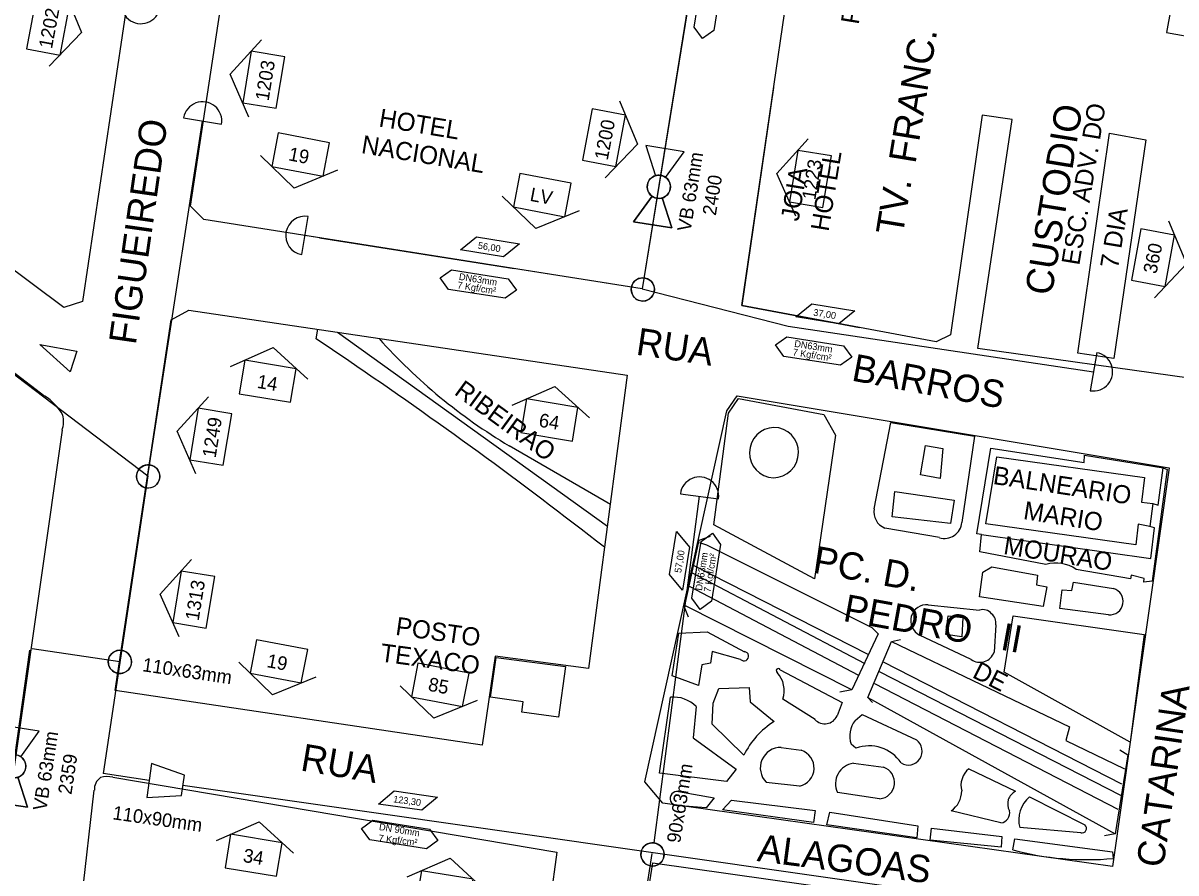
# Model space of a CAD drawing. Extents: x 325709 to 364434, y 7573432 to 7597073.
# Drawn here: x 338158.4 to 338412.3, y 7589570 to 7589757.3 of the extents above; entities that cross this region are included whole.
import ezdxf

# ---------------------------------------------------------------- set-up
doc = ezdxf.new("R2010")
doc.units = 0
for name, color, linetype in [('EDIFEXISTENT', 7, 'Continuous'), ('EDIFIDENTIF', 7, 'Continuous'), ('EDIFOBRAEXIS', 7, 'Continuous'), ('FORMATO', 7, 'Continuous'), ('LOGRADOURO', 7, 'Continuous'), ('LOGRADOURO_TEXTO', 7, 'Continuous'), ('NUM_REF', 7, 'Continuous'), ('SIMBOLO', 7, 'Continuous'), ('TEXTO', 7, 'Continuous'), ('TUBO_PEAD_GN_110', 7, 'Continuous'), ('TUBO_PEAD_GN_63', 7, 'Continuous'), ('TUBO_PEAD_GN_90', 7, 'Continuous'), ('VALVULA_PEAD_63', 7, 'Continuous'), ('VES - BLOQUEIIO', 7, 'Continuous')]:
    doc.layers.add(name, color=color, linetype=linetype)

# ---------------------------------------------------------------- blocks, each defined once
blk = doc.blocks.new('VALVULA_PEAD_DN_63')
at = {"layer": 'VALVULA_PEAD_63'}
for points in [[(-1.14, 0.57), (-4.25, 2.13), (-4.25, -2.13), (-1.14, -0.57)], [(-1.14, -0.57), (-4.25, -2.13), (-4.25, 2.13), (-1.14, 0.57)], [(1.14, -0.57), (4.25, -2.13), (4.25, 2.13), (1.14, 0.57)], [(1.14, -0.57), (4.25, -2.13), (4.25, 2.13), (1.14, 0.57)]]:
    blk.add_lwpolyline(points, dxfattribs=at)
blk.add_circle((0, 0), 1.28, dxfattribs=at)
for start, end in [(90, 270), (270, 90), (153.4349, 206.5651), (0, 26.5651), (333.4349, 0)]:
    blk.add_arc((0, 0), 1.28, start, end, dxfattribs=at)
blk = doc.blocks.new('INTERLIGACAO')
at = {"layer": 'SIMBOLO'}
blk.add_circle((0, 0), 1.28, dxfattribs=at)
for start, end in [(0, 180), (180, 0)]:
    blk.add_arc((0, 0), 1.28, start, end, dxfattribs=at)
blk = doc.blocks.new('NUM_REF')
at = {"layer": 'NUM_REF'}
blk.add_lwpolyline([(-4.3125, 0.9375), (0, 3.75), (4.3125, 0.9375)], dxfattribs=at)
blk.add_lwpolyline([(2.875, -1.875), (2.875, 1.875), (-2.875, 1.875), (-2.875, -1.875)], close=True, dxfattribs=at)

msp = doc.modelspace()

# ---------------------------------------------------------------- linework, layer by layer
at = {"layer": 'EDIFEXISTENT'}
for p, q in [((338323.68, 7589743.11), (338316.65, 7589695.04)), ((338390.66, 7589684.56), (338397.65, 7589733.03)), ((338397.65, 7589733.03), (338405.67, 7589731.58)), ((338405.67, 7589731.58), (338398.62, 7589683.41)), ((338223.69, 7589709.95), (338266.52, 7589703.2)), ((338316.65, 7589695.04), (338342.59, 7589690.19)), ((338398.62, 7589683.41), (338390.66, 7589684.56)), ((338356.03, 7589657.76), (338357.15, 7589664.2)), ((338357.15, 7589664.2), (338360.99, 7589663.58)), ((338360.99, 7589663.58), (338360.38, 7589656.96)), ((338370.46, 7589646.93), (338372.87, 7589661.74)), ((338372.87, 7589661.74), (338405.38, 7589657.14)), ((338360.38, 7589656.96), (338356.03, 7589657.76)), ((338405.38, 7589657.14), (338404.74, 7589651.72)), ((338349.81, 7589648.51), (338350.4, 7589654.06)), ((338350.4, 7589654.06), (338363.45, 7589652.17)), ((338363.45, 7589652.17), (338362.68, 7589647.01)), ((338404.74, 7589651.72), (338407.21, 7589651.43)), ((338407.21, 7589651.43), (338406.56, 7589646.34)), ((338362.68, 7589647.01), (338349.81, 7589648.51)), ((338403.45, 7589642.34), (338370.46, 7589646.93)), ((338403.97, 7589646.87), (338403.45, 7589642.34)), ((338406.56, 7589646.34), (338403.97, 7589646.87)), ((338304.04, 7589628.56), (338307.31, 7589643.34)), ((338307.31, 7589643.34), (338309.77, 7589644.2)), ((338304.97, 7589626.39), (338304.04, 7589628.56)), ((338361.62, 7589622.59), (338362.14, 7589626.66)), ((338362.14, 7589626.66), (338365.37, 7589626.29)), ((338365.37, 7589626.29), (338365.15, 7589622.07)), ((338345.31, 7589624.14), (338346.72, 7589622.72)), ((338346.72, 7589622.72), (338340.94, 7589610.37)), ((338344.4, 7589608.71), (338349.62, 7589621)), ((338349.62, 7589621), (338351.63, 7589621.49)), ((338365.15, 7589622.07), (338361.62, 7589622.59)), ((338261.32, 7589608.77), (338262.58, 7589617.5)), ((338262.58, 7589617.5), (338277.81, 7589615.53)), ((338277.81, 7589615.53), (338276.29, 7589604.36)), ((338340.94, 7589610.37), (338338.29, 7589609.88)), ((338268.55, 7589607.71), (338261.32, 7589608.77)), ((338268.2, 7589605.42), (338268.55, 7589607.71)), ((338345.45, 7589607.62), (338344.4, 7589608.71)), ((338276.29, 7589604.36), (338268.2, 7589605.42)), ((338401.67, 7589596.03), (338398.88, 7589578.64)), ((338399.94, 7589597.15), (338401.67, 7589596.03)), ((338398.88, 7589578.64), (338396.55, 7589578.2))]:
    msp.add_line(p, q, dxfattribs=at)
at = {"layer": 'EDIFOBRAEXIS'}
for p, q in [((338287.12, 7589646.39), (338227.63, 7589689.08)), ((338168.77, 7589680.42), (338162.09, 7589686.45)), ((338345.81, 7589650.28), (338349.48, 7589669.28)), ((338349.48, 7589669.28), (338367.93, 7589666.27)), ((338367.93, 7589666.27), (338365.14, 7589647.24)), ((338287.74, 7589651.18), (338265.42, 7589664.14)), ((338392.14, 7589662.08), (338409.52, 7589659.29)), ((338360.2, 7589643.9), (338348.16, 7589646.02)), ((338305.77, 7589636.16), (338343.74, 7589616.2)), ((338306.13, 7589637.78), (338344.44, 7589618.24)), ((338305.09, 7589633.22), (338342.38, 7589613.61)), ((338340.94, 7589610.37), (338304.16, 7589628.98)), ((338357.73, 7589629.12), (338369.05, 7589627.91)), ((338397.48, 7589626.91), (338386.69, 7589628.27)), ((338372.62, 7589624.72), (338372.26, 7589618.69)), ((338367.2, 7589617.07), (338355.82, 7589622.45)), ((338405.32, 7589622.54), (338402.25, 7589598.81)), ((338347.78, 7589616.52), (338400.32, 7589589.65)), ((338325.16, 7589614.79), (338338.79, 7589607.57)), ((338346.92, 7589614.41), (338400.08, 7589587.16)), ((338345.94, 7589611.76), (338399.53, 7589584.05)), ((338298.57, 7589592.02), (338300.98, 7589608.74)), ((338332.8, 7589603.84), (338325.74, 7589608.34)), ((338344.4, 7589608.71), (338398.88, 7589578.64)), ((338338.79, 7589607.57), (338337.65, 7589604.64)), ((338341.65, 7589603.59), (338343.19, 7589604.94)), ((338343.19, 7589604.94), (338355.16, 7589599.33)), ((338325.34, 7589597.68), (338329.74, 7589597.06)), ((338341.82, 7589597.51), (338340.75, 7589598.42)), ((338341.25, 7589594.2), (338347.89, 7589593.31)), ((338366.7, 7589592.99), (338376.99, 7589588.02)), ((338329.36, 7589589.15), (338322.07, 7589589.99)), ((338302.72, 7589587.95), (338310.61, 7589586.57)), ((338347.04, 7589586.37), (338337.76, 7589587.78)), ((338380.07, 7589586.78), (338392.24, 7589580.62)), ((338373.76, 7589581.09), (338362.77, 7589583.72)), ((338391.33, 7589578.86), (338377.91, 7589580.01))]:
    msp.add_line(p, q, dxfattribs=at)
for points in [[(338230.1, 7589682.84), (338222.94, 7589687.69), (338223.28, 7589689.81)], [(338162.09, 7589686.45), (338170.21, 7589684.98), (338168.77, 7589680.42)], [(338310.51, 7589646.73), (338313.77, 7589671.33), (338315.98, 7589674.56), (338334.76, 7589671.06)], [(338334.76, 7589671.06), (338337.29, 7589666.47), (338332.72, 7589634.83), (338310.51, 7589646.73)], [(338383.66, 7589637.97), (338369.13, 7589640.75), (338369.5, 7589644.61), (338368.43, 7589644.76), (338371.52, 7589663.59), (338392.07, 7589660.43), (338392.14, 7589662.08)], [(338409.52, 7589659.29), (338410.37, 7589658.89), (338407.09, 7589634.32)], [(338407.21, 7589651.43), (338408.38, 7589651.08), (338409.52, 7589659.29)], [(338369.5, 7589644.61), (338406.74, 7589639.32), (338407.61, 7589646.04), (338406.56, 7589646.34)], [(338307.34, 7589642.81), (338308.9, 7589642.32), (338345.31, 7589624.14)], [(338383.05, 7589628.77), (338369.06, 7589630.88), (338369.76, 7589636.27), (338371.76, 7589637.48), (338381.84, 7589635.65), (338381.61, 7589633.49), (338383.83, 7589633.07), (338383.05, 7589628.77)], [(338407.09, 7589634.32), (338405.23, 7589634.13), (338405.28, 7589634.9), (338402.45, 7589635.62), (338402.28, 7589634.86), (338390.35, 7589636.9)], [(338386.69, 7589628.27), (338387.21, 7589632.42), (338389.35, 7589632.27), (338389.77, 7589634.11), (338398.55, 7589632.71)], [(338402.25, 7589598.81), (338374.43, 7589614.27), (338376.48, 7589626.69), (338405.32, 7589622.54)], [(338301.32, 7589613.44), (338302.81, 7589622.88), (338309.01, 7589623.13), (338317.24, 7589618.78)], [(338349.62, 7589621), (338388.89, 7589602.25), (338388.06, 7589599.19), (338400.97, 7589592.96)], [(338316.41, 7589617.08), (338310.15, 7589618.84), (338309.75, 7589616.22), (338307.84, 7589615.88), (338307.15, 7589611.35), (338301.32, 7589613.44)], [(338317.14, 7589595.98), (338310.12, 7589602.79), (338310.36, 7589607.47), (338311.65, 7589610.7), (338318.31, 7589610.91), (338318.52, 7589607.75), (338323.77, 7589603.37)], [(338306.63, 7589606.7), (338305.96, 7589599.83), (338315.45, 7589592.9), (338313.32, 7589590.17), (338298.57, 7589592.02)], [(338310.61, 7589586.57), (338308.86, 7589584.41), (338302.23, 7589584.92)], [(338312.42, 7589583.91), (338314.38, 7589586.1), (338332.84, 7589583.78), (338332.44, 7589581.13), (338312.42, 7589583.91)], [(338335.39, 7589580.61), (338336.07, 7589583.43), (338355.45, 7589580.39), (338355.26, 7589577.78), (338335.39, 7589580.61)], [(338358.19, 7589577.25), (338358.48, 7589579.87), (338373.95, 7589578.07), (338373.8, 7589575.68), (338358.19, 7589577.25)], [(338376.4, 7589575.1), (338376.79, 7589577.57), (338398.34, 7589574.67), (338398.5, 7589573.22)]]:
    msp.add_lwpolyline(points, dxfattribs=at)
for centre, radius, start, end in [((338328.64, 7589770.03), 123.32, 221.8386, 239.1593), ((337642.07, 7588816.75), 1046.84, 52.01007, 55.82538), ((338323.95, 7589662.6), 5.57, 80.9838, 255.1417), ((338323.6, 7589662.68), 5.57, 258.8377, 77.2878), ((338349.67, 7589649.63), 3.92, 170.4485, 247.3515), ((338361.29, 7589647.61), 3.87, 253.6354, 354.5386), ((338385.89, 7589630.5), 7.8, 55.1749, 106.642), ((338397.71, 7589629.87), 2.97, 265.4447, 73.5827), ((338357.41, 7589625.6), 3.53, 84.7733, 243.2624), ((338369.84, 7589625.67), 2.37, 38.6962, 109.5102), ((338369.89, 7589625.08), 2.75, 352.5071, 48.9931), ((338317.16, 7589617.77), 1.02, 222.468, 85.4762), ((338369.14, 7589619.72), 3.28, 233.8407, 341.6812), ((338324.74, 7589614.57), 0.473, 27.7916, 235.8636), ((338320.12, 7589610.18), 5.91, 341.8635, 42.578), ((338301.66, 7589601.78), 6.99, 44.6822, 95.6153), ((338333.45, 7589588.01), 18.15, 122.214, 153.9817), ((338334.96, 7589605.84), 2.95, 222.8388, 335.9872), ((338345.67, 7589600.23), 5.24, 140.1379, 200.1376), ((338325.25, 7589593.18), 4.5, 88.8086, 224.9993), ((338344.75, 7589589.67), 8.37, 33.3043, 110.4785), ((338353.34, 7589596.87), 3.06, 238.5568, 53.5259), ((338328.51, 7589593.16), 4.09, 282.0017, 72.4962), ((338341.84, 7589589.72), 4.52, 97.5431, 205.4331), ((338346.74, 7589589.93), 3.57, 274.8968, 71.2929), ((338369.62, 7589589.35), 4.67, 128.6421, 195.414), ((338302.42, 7589586.44), 1.54, 78.429, 262.8783), ((338359.86, 7589588.1), 5.25, 303.5456, 0.0425), ((338378.34, 7589585.22), 3.11, 115.7146, 208.4185), ((338384.19, 7589581.73), 6.52, 129.2425, 195.3126), ((338373.56, 7589583.2), 2.12, 275.378, 14.8783), ((338391.58, 7589579.85), 1.02, 255.9549, 49.3276), ((338392.75, 7589636.43), 63.47, 255.0683, 275.1926)]:
    msp.add_arc(centre, radius, start, end, dxfattribs=at)
at = {"layer": 'LOGRADOURO'}
for p, q in [((338188.71, 7589811.63), (338171.42, 7589695.95)), ((338195.26, 7589716.93), (338208.92, 7589807.67)), ((338310.48, 7589796.44), (338294.75, 7589698.75)), ((338316.65, 7589695.04), (338330.98, 7589793.1)), ((338111.28, 7589714.69), (338163.14, 7589675.11)), ((338359.52, 7589687.02), (338316.65, 7589695.04)), ((338178.63, 7589610.24), (338191, 7589691.88)), ((338415.76, 7589678.98), (338368.65, 7589685.54)), ((338291.45, 7589679.69), (338282.94, 7589615.06)), ((338166.96, 7589667.55), (338143.19, 7589501.91)), ((338259.48, 7589598.2), (338178.63, 7589610.24)), ((338178.16, 7589591.14), (338275.9, 7589574.59)), ((338169.04, 7589544.48), (338174.06, 7589588.26)), ((338275.9, 7589574.59), (338269.3, 7589525.28)), ((338286.19, 7589501.91), (338297.06, 7589572.25))]:
    msp.add_line(p, q, dxfattribs=at)
for points in [[(338171.42, 7589695.95), (338167.32, 7589694.58), (338019.9, 7589804.84)], [(338369.6, 7589736.99), (338362.66, 7589688.62), (338359.52, 7589687.02)], [(338368.65, 7589685.54), (338376.23, 7589736.06), (338369.6, 7589736.99)], [(338294.75, 7589698.75), (338198.16, 7589713.98), (338195.26, 7589716.93)], [(338191, 7589691.88), (338194.89, 7589694.02), (338291.45, 7589679.69)], [(338315.62, 7589675.17), (338410.82, 7589659.3), (338398.32, 7589571.45), (338299.26, 7589585.38), (338295.35, 7589590.11), (338313.41, 7589671.83), (338315.62, 7589675.17)], [(338282.94, 7589615.06), (338262.37, 7589617.78), (338259.48, 7589598.2)], [(338297.06, 7589572.25), (338390.92, 7589558.99), (338394.03, 7589554.04)]]:
    msp.add_lwpolyline(points, dxfattribs=at)
for centre, radius, start, end in [((338156.76, 7589665.09), 11.88, 29.3543, 57.491), ((338161.27, 7589669.49), 6.01, 341.1931, 13.7625), ((338177.19, 7589588.47), 3.13, 124.3846, 183.8509), ((338176.97, 7589585.12), 6.13, 78.8715, 104.678)]:
    msp.add_arc(centre, radius, start, end, dxfattribs=at)
at = {"layer": 'SIMBOLO'}
for points in [[(338306.18, 7589756.36), (338308.2, 7589768.82), (338310.71, 7589770.63), (338310.71, 7589770.63), (338312.52, 7589768.13), (338310.5, 7589755.66), (338307.99, 7589753.85), (338307.99, 7589753.85)], [(338264.21, 7589705.78), (338254.72, 7589707.28), (338258.21, 7589710.15), (338267.7, 7589708.65)], [(338252.73, 7589702.93), (338265.2, 7589700.96), (338267.02, 7589698.46), (338267.02, 7589698.46), (338264.52, 7589696.64), (338252.05, 7589698.6), (338250.23, 7589701.11), (338250.23, 7589701.11)], [(338338.08, 7589691.03), (338328.59, 7589692.52), (338332.08, 7589695.39), (338341.57, 7589693.89)], [(338326.6, 7589688.17), (338339.07, 7589686.2), (338340.89, 7589683.7), (338340.89, 7589683.7), (338338.39, 7589681.88), (338325.92, 7589683.85), (338324.1, 7589686.35), (338324.1, 7589686.35)], [(338305.12, 7589641.79), (338303.59, 7589632.31), (338300.74, 7589635.81), (338302.27, 7589645.29)], [(338305.68, 7589630.59), (338307.69, 7589643.06), (338310.2, 7589644.87), (338310.2, 7589644.87), (338312.01, 7589642.36), (338309.99, 7589629.89), (338307.49, 7589628.08), (338307.49, 7589628.08)], [(338185.62, 7589586.69), (338193.25, 7589587.11), (338193.89, 7589591.57), (338186.68, 7589594.11)], [(338246.19, 7589583.83), (338236.67, 7589585.16), (338240.11, 7589588.09), (338249.63, 7589586.76)], [(338235.42, 7589581.67), (338247.88, 7589579.66), (338249.7, 7589577.15), (338249.7, 7589577.15), (338247.19, 7589575.34), (338234.72, 7589577.35), (338232.91, 7589579.85), (338232.91, 7589579.85)]]:
    msp.add_lwpolyline(points, close=True, dxfattribs=at)
at = {"layer": 'TUBO_PEAD_GN_110'}
for p in [(338185.83, 7589657.54), (338186.15, 7589590.4)]:
    msp.add_line(p, (338176.02, 7589591.92), dxfattribs=at)
msp.add_lwpolyline([(337953.1, 7589834.11), (337996.7, 7589801.26), (338185.83, 7589657.54)], dxfattribs=at)
at = {"layer": 'TUBO_PEAD_GN_63'}
for p, q in [((338319.08, 7589849.08), (338294.75, 7589698.75)), ((338193.71, 7589736.4), (338202.1, 7589734.97)), ((338219.74, 7589706.27), (338221.19, 7589714.65)), ((338294.75, 7589698.75), (338220.46, 7589710.46)), ((338394.84, 7589684.66), (338393.39, 7589676.28)), ((338303.14, 7589653.57), (338311.57, 7589652.46)), ((338297.4, 7589576.64), (338307.35, 7589653.02)), ((338159.8, 7589619.12), (338141.55, 7589489.86)), ((338160.35, 7589619.49), (338179.71, 7589616.6)), ((338259.51, 7589332.64), (338296.9, 7589574.35))]:
    msp.add_line(p, q, dxfattribs=at)
for points in [[(338185.82, 7589657.55), (338185.83, 7589657.54), (338197.9, 7589735.69)], [(338294.75, 7589698.75), (338326.89, 7589690.52), (338394.11, 7589680.47)]]:
    msp.add_lwpolyline(points, dxfattribs=at)
for centre, start, end in [((338184.33, 7589761.38), 169.7565, 349.7565), ((338197.9, 7589735.69), 350.3615, 170.3615), ((338220.46, 7589710.46), 80.1988, 260.1988), ((338394.11, 7589680.47), 260.1988, 80.1988), ((338307.35, 7589653.02), 352.5411, 172.5411)]:
    msp.add_arc(centre, 4.25, start, end, dxfattribs=at)
at = {"layer": 'TUBO_PEAD_GN_90'}
msp.add_line((338193.57, 7589589.34), (338415.28, 7589557.67), dxfattribs=at)

# ---------------------------------------------------------------- block references
at = {"layer": 'FORMATO'}
for p, xscale, yscale, rotation in [((338414.95, 7589760.17), 1.9999999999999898, 1.9999999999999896, -100.3090999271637), ((338163.9, 7589756.58), 1.9999999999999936, 1.9999999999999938, -100.70632208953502), ((338211.36, 7589744.78), 1.9999999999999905, 1.9999999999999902, 80.75268328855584), ((338286.31, 7589732.02), 1.9999999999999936, 1.9999999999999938, -100.70632208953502), ((338219.5, 7589728.3), 1.9999999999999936, 1.9999999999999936, 169.19964910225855), ((338331.78, 7589722.95), 1.9999999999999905, 1.9999999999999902, 80.75268328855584), ((338272.74, 7589719.37), 1.9999999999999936, 1.9999999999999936, 169.19964910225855), ((338407.24, 7589705.59), 1.9999999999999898, 1.9999999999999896, -100.3090999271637), ((338212.24, 7589678.37), 1.9999999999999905, 1.9999999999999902, -9.391824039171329), ((338274.3, 7589669.83), 1.9999999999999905, 1.9999999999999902, -9.391824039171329), ((338199.69, 7589666.14), 1.9999999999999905, 1.9999999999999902, 80.75268328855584), ((338195.95, 7589630.25), 1.9999999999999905, 1.9999999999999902, 80.75268328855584), ((338214.71, 7589616.66), 1.9999999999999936, 1.9999999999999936, 169.19964910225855), ((338250.24, 7589611.47), 1.9999999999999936, 1.9999999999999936, 169.19964910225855), ((338209.15, 7589573.93), 1.9999999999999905, 1.9999999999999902, -9.391824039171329), ((338251.19, 7589565.89), 1.9999999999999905, 1.9999999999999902, -9.391824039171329)]:
    msp.add_blockref('NUM_REF', p, dxfattribs=dict(at, xscale=xscale, yscale=yscale, rotation=rotation))
at = {"layer": 'SIMBOLO'}
for p, xscale, yscale, rotation in [((338294.87, 7589698.59), 2.0000000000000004, 1.9999999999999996, 22.031790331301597), ((338185.92, 7589657.4), 2, 2, -8.011999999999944), ((338179.69, 7589616.54), 2, 2, -8.449022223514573), ((338297, 7589574.12), 1.9999999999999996, 1.9999999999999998, 80.91199999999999)]:
    msp.add_blockref('INTERLIGACAO', p, dxfattribs=dict(at, xscale=xscale, yscale=yscale, rotation=rotation))
at = {"layer": 'VES - BLOQUEIIO'}
for p, xscale, yscale, rotation in [((338298.4, 7589721.2), 1.9999999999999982, 1.9999999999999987, 80.91156229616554), ((338156.41, 7589593.54), 1.999999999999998, 1.9999999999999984, 81.36089406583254)]:
    msp.add_blockref('VALVULA_PEAD_DN_63', p, dxfattribs=dict(at, xscale=xscale, yscale=yscale, rotation=rotation))

# ---------------------------------------------------------------- texts
for s, rotation, p in [('1202', 79.2937, (338164.72, 7589751.48)), ('1203', 80.7527, (338212.44, 7589740)), ('1200', 79.2937, (338287.13, 7589726.92)), ('19', 349.1996, (338216.68, 7589727.05)), ('VB 63mm', 80.9116, (338305.39, 7589711.2)), ('1223', 80.7527, (338332.86, 7589718.17)), ('2400', 80.9116, (338310.95, 7589714.74)), ('LV', 349.1996, (338269.85, 7589718.14)), ('360', 78.2244, (338407.99, 7589701.87)), ('14', 350.6082, (338209.76, 7589676.92)), ('64', 350.6082, (338271.82, 7589668.38)), ('1249', 80.7527, (338200.77, 7589661.36)), ('1313', 80.7527, (338197.03, 7589625.48)), ('19', 349.1996, (338211.89, 7589615.41)), ('110x63mm', 351.551, (338184.5, 7589614.5)), ('85', 349.1996, (338247.42, 7589610.22)), ('VB 63mm', 81.3609, (338163.48, 7589583.6)), ('2359', 81.3609, (338169.01, 7589587.18)), ('90x63mm', 80.912, (338303.09, 7589576.48)), ('34', 350.6082, (338206.67, 7589572.48))]:
    msp.add_text(s, height=3, rotation=rotation).set_placement(p)
at = {"layer": 'EDIFIDENTIF'}
for s, rotation, p in [('POCOS DE', 80.6301, (338342.4, 7589756.82)), ('HOTEL', 350.6301, (338236.56, 7589734.51)), ('ESC. ADV. DO', 80.6301, (338391, 7589703.76)), ('NACIONAL', 350.6301, (338232.7, 7589728.65)), ('HOTEL', 80.6301, (338335.77, 7589711.22)), ('JOIA', 80.6301, (338329.19, 7589713.45)), ('7 DIA', 80.6301, (338399.52, 7589703.04)), ('RIBEIRAO', 323.8209, (338253.12, 7589675.61)), ('BALNEARIO', 351.4693, (338371.86, 7589655.74)), ('MARIO', 350.9912, (338378.52, 7589648.02)), ('MOURAO', 350.9912, (338374.15, 7589640.32)), ('POSTO', 351.9861, (338240.25, 7589622.51)), ('TEXACO', 352.3458, (338236.88, 7589616.65)), ('DE', 333.0411, (338367.22, 7589613.23))]:
    msp.add_text(s, height=4, rotation=rotation, dxfattribs=at).set_placement(p)
at = {"layer": 'LOGRADOURO_TEXTO'}
for s, rotation, p in [('FRANC.', 80.7233, (338354.93, 7589726.15)), ('CUSTODIO', 80.7233, (338384.94, 7589697.06)), ('FIGUEIREDO', 81.8831, (338183.18, 7589686.24)), ('TV.', 80.7233, (338352.11, 7589710.3)), ('RUA', 351.5575, (338293.17, 7589684.24)), ('BARROS', 349.4021, (338340.65, 7589678.54)), ('PC. D.', 349.6965, (338332.11, 7589636.22)), ('PEDRO   II', 349.6754, (338338.77, 7589625.58)), ('CATARINA', 81.7587, (338409.51, 7589571.02)), ('RUA', 350.3915, (338219.27, 7589592.64)), ('ALAGOAS', 352.5744, (338319.89, 7589572.67))]:
    msp.add_text(s, height=6, rotation=rotation, dxfattribs=at).set_placement(p)
at = {"layer": 'TEXTO'}
for s, height, rotation, p in [('56,00', 1.5, 351.0362, (338258.46, 7589707.58)), ('DN63mm', 1.5, 351.0362, (338254.29, 7589700.72)), ('7 Kgf/cm²', 1.5, 351.0362, (338253.94, 7589698.85)), ('37,00', 1.5, 351.0362, (338332.34, 7589692.83)), ('DN63mm', 1.5, 351.0362, (338328.16, 7589685.96)), ('7 Kgf/cm²', 1.5, 351.0362, (338327.81, 7589684.09)), ('57,00', 1.5, 80.8049, (338303.3, 7589636.05)), ('DN63mm', 1.5, 80.8049, (338307.89, 7589632.15)), ('7 Kgf/cm²', 1.5, 80.8049, (338309.76, 7589631.79)), ('123,30', 1.5, 352.045, (338239.83, 7589585.61)), ('110x90mm', 3, 351.8702, (338177.96, 7589581.87)), ('DN 90mm', 1.5, 350.8522, (338236.69, 7589579.5)), ('7 Kgf/cm²', 1.5, 353.407, (338236.6, 7589577))]:
    msp.add_text(s, height=height, rotation=rotation, dxfattribs=at).set_placement(p)

doc.saveas('drawing.dxf')
